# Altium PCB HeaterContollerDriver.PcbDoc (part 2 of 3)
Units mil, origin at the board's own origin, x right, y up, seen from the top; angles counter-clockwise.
Board outline 11550 x 4775 mil, 6 copper layers (Top Layer, GND1, P, N, GND2, Bottom Layer), stack 62.668 mil thick; 274 components, 133 nets, 711 pads, 145 vias.
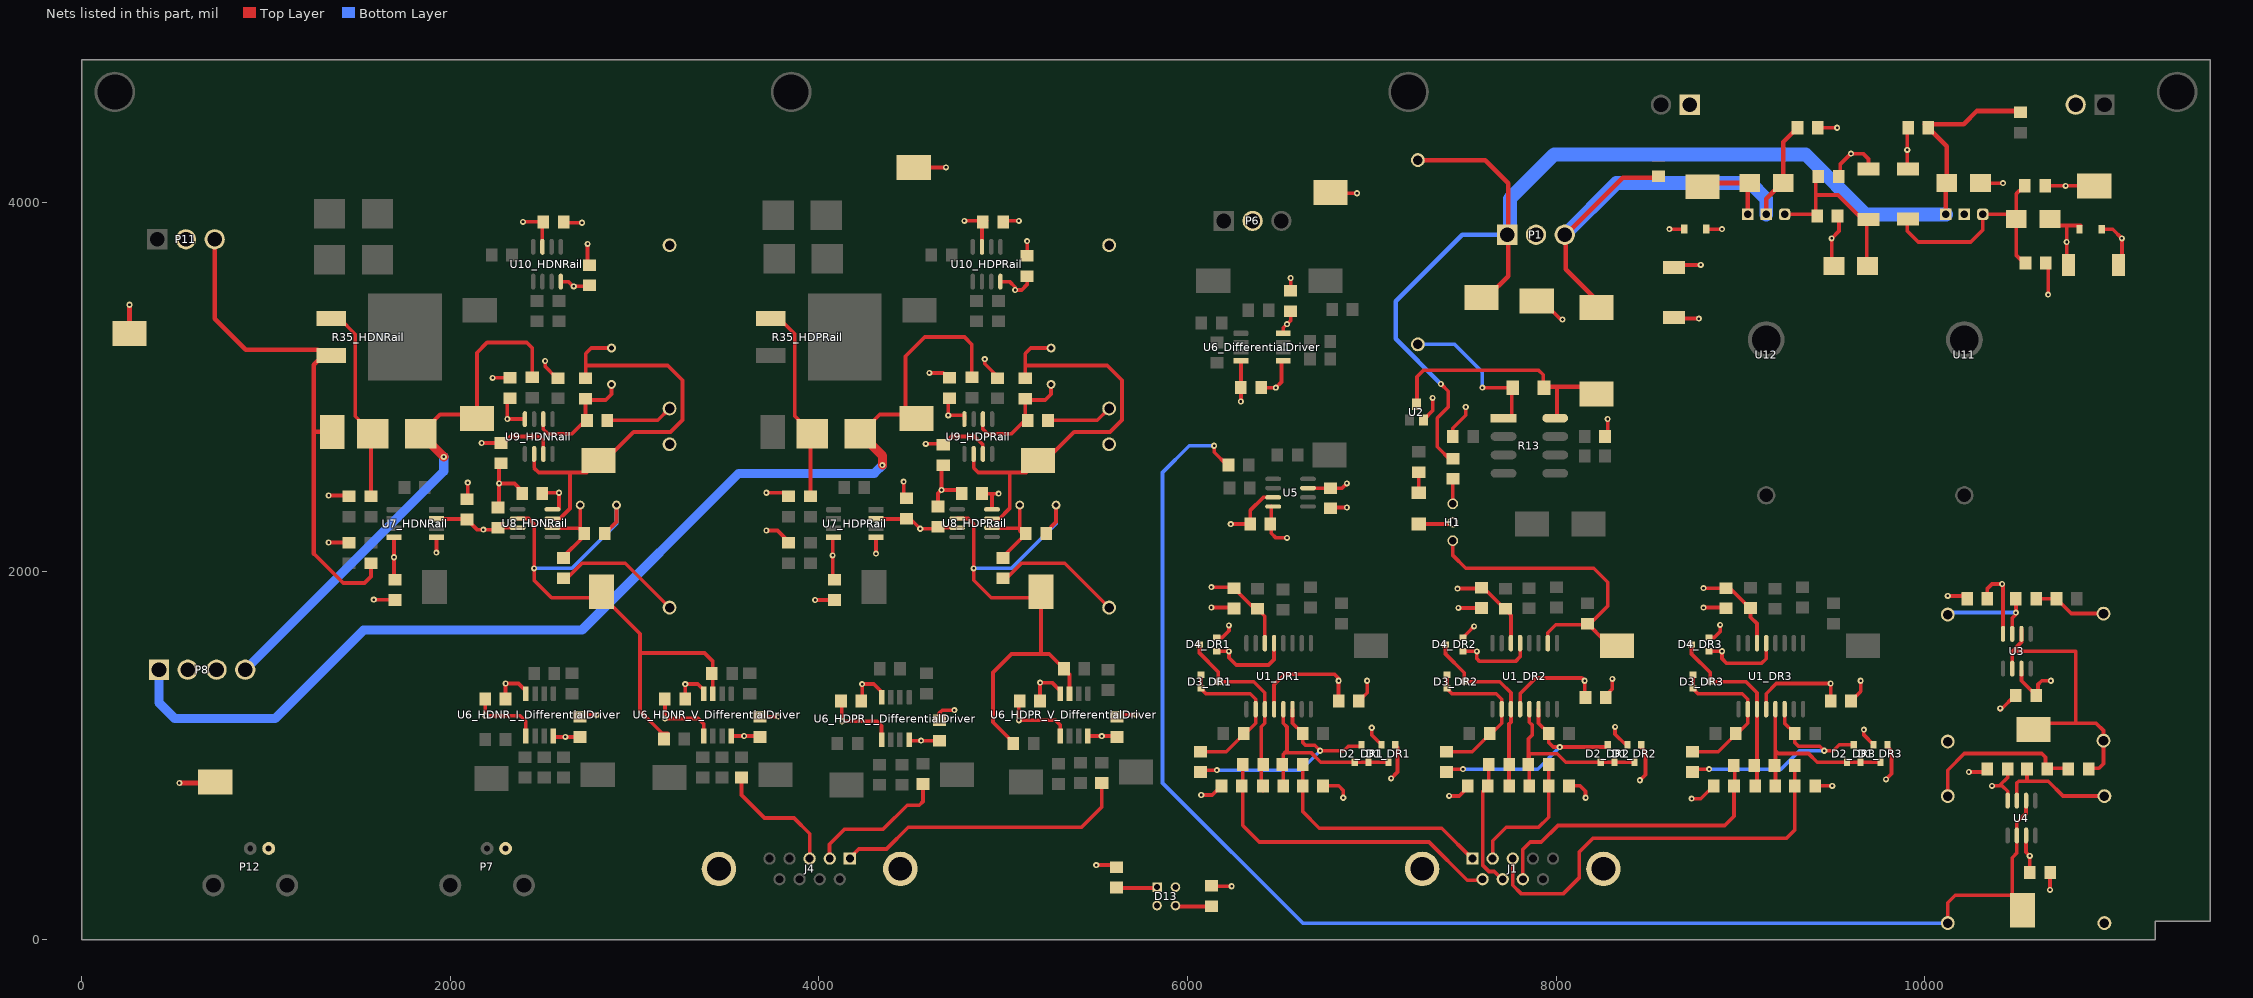
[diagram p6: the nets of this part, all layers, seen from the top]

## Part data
C1_DR1 C1_DR2 C1_DR3: library part MYCAP, "CAP 3.3nF 50V PPS 1206", Digikey Part Number=PCF1302CT-ND, Manufacturers Part Number=ECH-U1H332GX5, Tolerance=3%
C2_DR1 C2_DR2 C2_DR3 C3_DR1 C3_DR2 C3_DR3 C6 C7 C10 C11 C12 C13 C14_DifferentialDriver C14_HDNR_I_DifferentialDriver C14_HDNR_V_DifferentialDriver C14_HDPR_I_DifferentialDriver C14_HDPR_V_DifferentialDriver C15_DifferentialDriver C15_HDNR_I_DifferentialDriver C15_HDNR_V_DifferentialDriver C15_HDPR_I_DifferentialDriver C15_HDPR_V_DifferentialDriver C16_HDNRail C16_HDPRail C17_HDNRail C17_HDPRail C20_HDNRail C20_HDPRail C21_HDNRail C21_HDPRail C24_HDNRail C24_HDPRail C25_HDNRail C25_HDPRail C26_HDNRail C26_HDPRail C27_HDNRail C27_HDPRail C29 C33: library part MYCAP, "CAP 1.0UF 50V CERAMIC F 1206", Digikey Part Number=1276-1068-1-ND, Tolerance=5%
C4 C5 C8 C9: library part CAP_Radial_3.9uF_250v, Digikey Part Number=P10986-ND, Manufacturers Part Number=ECQ-E2395JB, Supplier Part Number 1=P14641-ND, Tolerance=3%
C18_HDNRail C18_HDPRail C19_HDNRail C19_HDPRail: library part CAP_Radial_6800pF_Polyester, Digikey Part Number=399-19323-1-ND, Manufacturers Part Number=R82EC1680DQ50J, Tolerance=5%
C22_HDNRail C22_HDPRail C23_HDNRail C23_HDPRail: library part CAP_10uF_Polyester, "Cap Film 10uF 100v +-5% 0.886inch", Digikey Part Number=P14629-ND, Manufacturers Part Number=ECQ-E1106JF, Tolerance=3%
C28 C30 C31 C32: library part CAP_2917_10µF_50v, Digikey Part Number=478-13267-1-ND, Manufacturers Part Number=TCJD106M050R0120, Tolerance=5%
D1_DR1 D1_DR2 D1_DR3 D2_DR1 D2_DR2 D2_DR3 D3_DR1 D3_DR2 D3_DR3 D4_DR1 D4_DR2 D4_DR3: "DUAL SERIES DIODE.", Digikey Part Number=BAS70-04LT1GOSCT-ND, Manufacturers Part Number=BAS70-04LT1G
D5 D6: library part DIODE_SE20AFJ-M3/6A, Digikey Part Number=SE20AFJ-M3/6AGICT-ND, Manufacturers Part Number=SE20AFJ-M3/6A
D7 D8 D10 D12: library part DIODE_S1BB, Digikey Part Number=S1BB-FDICT-ND, Manufacturers Part Number=S1BB-13-F
D9 D11: library part "DIODE RB160M-60TR", Digikey Part Number=RBR1MM60ATFCT-ND, Manufacturers Part Number=RBR1MM60ATFTR
D13: library part "Dual Stacked LED", "Dual Green LED", Supplier Part Number 1=67-1321-ND
F1_HDNRail F1_HDPRail F2_HDNRail F2_HDPRail F3_HDNRail F3_HDPRail: library part "SMD FUSE 1AMP", Digikey Part Number=F1303CT-ND, Manufacturers Part Number=0154001.DRT, Supplier Part Number 1=F1222CT-ND
H1: library part Header_3P, Digikey Part Number=S1011EC-03-ND, Manufacturers Part Number=PRPC003SAAN-RC
J1: library part DB9M, "Plug Assembly, 9 Position, Right Angle, .318 Series", Supplier Part Number 1=664-6E17C009PAJ121-ND
J4: library part "D Connector 9", "Receptacle Assembly, 9 Position, Right Angle", Digikey Part Number=A32117-ND, Manufacturers Part Number=5747844-4
P1 P6 P11: "Header, 3-Pin, Right Angle", Digikey Part Number=WM5236-ND
P7 P12: "BNC Straight Away Connector", Digikey Part Number=A144890-ND, Manufacturers Part Number=5227161-7
P8: "Header, 4-Pin, Right Angle", Digikey Part Number=WM5237-ND
P13 P14: library part "Header 2p 0.156inch", Digikey Part Number=A31676-ND, Manufacturers Part Number=3-641208-2, Supplier Part Number 1=A31688-ND
R1_DR1 R1_DR2 R1_DR3 R11_DR1 R11_DR2 R11_DR3: library part MYRES, "Resistor", 'Manufacturers Part Number=ERA-8AEB3011V, Digikey Part Number=P3.01KBCCT-ND, Tolerance=0.1%
R2_DR1 R2_DR2 R2_DR3 R10_DR1 R10_DR2 R10_DR3: library part MYRES, "Resistor", 'Manufacturers Part Number=ERA-8AEB104V, Digikey Part Number=P100KBCCT-ND, Tolerance=0.1%
R3_DR1 R3_DR2 R3_DR3 R9_DR1 R9_DR2 R9_DR3: library part MYRES, 'Manufacturers Part Number=ERA-8AEB3011V, Digikey Part Number=P2.26KBCCT-ND, Manufacturers Part Number=ERA-8AEB2261V, Tolerance=0.1%
R4_DR1 R4_DR2 R4_DR3 R7_DR1 R7_DR2 R7_DR3: library part MYRES, "Resistor", 'Manufacturers Part Number=ERA-8AEB102V, Digikey Part Number=P1.0KBCCT-ND, Tolerance=0.1%
R5_DR1 R5_DR2 R5_DR3 R8_DR1 R8_DR2 R8_DR3 R14 R15 R16 R28_DifferentialDriver R28_HDNR_I_DifferentialDriver R28_HDNR_V_DifferentialDriver R28_HDPR_I_DifferentialDriver R28_HDPR_V_DifferentialDriver R31_DifferentialDriver R31_HDNR_I_DifferentialDriver R31_HDNR_V_DifferentialDriver R31_HDPR_I_DifferentialDriver R31_HDPR_V_DifferentialDriver R44_HDNRail R44_HDPRail R45_HDNRail R45_HDPRail R46_HDNRail R46_HDPRail: library part Res3, "Resistor", Digikey Part Number=HCJ1206ZT0R00CT-ND, Tolerance=0.1%
R6_DR1 R6_DR2 R6_DR3: library part MYRES, "Resistor", Tolerance=0.1%
R12: library part Axial_TH_Res_1.30K_5W, Digikey Part Number=1.3KW-5-ND, Manufacturers Part Number=SQP500JB-1K3, Tolerance=0.1%
R13: library part RELAY_G6K-2F-TR-DC12, Digikey Part Number=Z113-ND, Manufacturers Part Number="G6K-2F DC12", Tolerance=0.1%
R17 R18: library part 1206_Res_3.9K, Digikey Part Number=P3.9KBCCT-ND, Manufacturers Part Number=ERA-8AEB392V, Tolerance=0.1%
R19 R20 R21 R22: library part MYRES, "39.2K Film Resistor", 'Manufacturers Part Number=ERA-8AEB3922V, Digikey Part Number=P39.2KBCCT-ND, Tolerance=0.1%
R23 R24 R25 R42_HDNRail R42_HDPRail R51 R52 R53 R54: library part 1206_Res_10K, "SMD 1206 Resistor 10K 0.25W 0.1%", Digikey Part Number=RNCP1206FTD10K0CT-ND, Manufacturers Part Number=RNCP1206FTD10K0, Tolerance=0.1%
R26_DifferentialDriver R26_HDNR_I_DifferentialDriver R26_HDNR_V_DifferentialDriver R26_HDPR_I_DifferentialDriver R26_HDPR_V_DifferentialDriver R27_DifferentialDriver R27_HDNR_I_DifferentialDriver R27_HDNR_V_DifferentialDriver R27_HDPR_I_DifferentialDriver R27_HDPR_V_DifferentialDriver R29_DifferentialDriver R29_HDNR_I_DifferentialDriver R29_HDNR_V_DifferentialDriver R29_HDPR_I_DifferentialDriver R29_HDPR_V_DifferentialDriver R30_DifferentialDriver R30_HDNR_I_DifferentialDriver R30_HDNR_V_DifferentialDriver R30_HDPR_I_DifferentialDriver R30_HDPR_V_DifferentialDriver R43_HDNRail R43_HDPRail: library part Res3, "Resistor", 'Manufacturers Part Number=TNPW12064K99BEEA, Digikey Part Number=TNP4.99KACCT-ND, Tolerance=0.1%
R32_HDNRail R32_HDPRail: library part 1206_Res_5.49K, Digikey Part Number=P2.61KBCCT-ND, Manufacturers Part Number=ERA-8AEB2611V, Tolerance=0.1%
R33_HDNRail R33_HDPRail R34_HDNRail R34_HDPRail R36_HDNRail R36_HDPRail R37_HDNRail R37_HDPRail: library part 1206_Res_100K, Digikey Part Number=P100KBCCT-ND, Manufacturers Part Number=ERA-8AEB104V, Tolerance=0.1%
R35_HDNRail R35_HDPRail: library part RES_D2PAK_1R00, 'Manufacturers Part Number=PWR263S-35-1R00F, Digikey Part Number=PWR163S-25-R100FECT-ND, Manufacturers Part Number=PWR163S-25-R100FE, Supplier Part Number 1=PWR263S-35-1R00F-ND, Tolerance=0.1%
R38_HDNRail R38_HDPRail R39_HDNRail R39_HDPRail: library part 1206_Res_23.2K, Digikey Part Number=P23.2KBCDKR-ND, Manufacturers Part Number=ERA-8AEB2322V, Supplier Part Number 1=P23.2KBCCT-ND, Tolerance=0.1%
R40_HDNRail R40_HDPRail R41_HDNRail R41_HDPRail: library part 1206_Res_1.58K, Digikey Part Number=P1.58KBCDKR-ND, Manufacturers Part Number=ERA-8AEB1581V, Tolerance=0.1%
R47: library part 1206_Res_249, Digikey Part Number=P249BCCT-ND, Manufacturers Part Number=ERA-8AEB2490V, Tolerance=0.1%
R48: library part 1206_Res_2.74K, Digikey Part Number=P2.74KBCCT-ND, Manufacturers Part Number=ERA-8AEB2741V, Tolerance=0.1%
R49: library part 1206_Res_1.33K, Digikey Part Number=P1.33KBCCT-ND, Manufacturers Part Number=ERA-8AEB1331V, Tolerance=0.1%
R50: library part 1206_Res_120R, Digikey Part Number=P120BCCT-ND, Manufacturers Part Number=ERA-8AEB121V, Tolerance=0.1%
TP1_DR1 TP1_DR2 TP1_DR3 TP2 TP3 TP4 TP5 TP6 TP7 TP8_DifferentialDriver TP8_HDNR_I_DifferentialDriver TP8_HDNR_V_DifferentialDriver TP8_HDPR_I_DifferentialDriver TP8_HDPR_V_DifferentialDriver TP9_DifferentialDriver TP9_HDNR_I_DifferentialDriver TP9_HDNR_V_DifferentialDriver TP9_HDPR_I_DifferentialDriver TP9_HDPR_V_DifferentialDriver TP10_HDNRail TP10_HDPRail TP11_HDNRail TP11_HDPRail TP12_HDNRail TP12_HDPRail TP13_HDNRail TP13_HDPRail TP14_HDNRail TP14_HDPRail TP15 TP16 TP17 TP18 TP19 TP20_HDNRail TP20_HDPRail TP21 TP22 TP23 TP24: "PCB Testpoint", 'Manufacturers Part Number=5016, Digikey Part Number=36-5016CT-ND
U1_DR1 U1_DR2 U1_DR3: "Quad Low Noise, High-Speed Precision Operational Amplifier", 'Manufacturers Part Number=LT1125CSW#PBF, Digikey Part Number=505-LT1125CSW#PBF-ND
U2: library part MMBT2222A_NPN, 'Manufacturers Part Number=MMBT2222A, Digikey Part Number=MMBT2222ALT1GOSCT-ND
U3 U4 U5 U8_HDNRail U8_HDPRail U9_HDNRail U9_HDPRail U10_HDNRail U10_HDPRail: library part ADOP27AQ, "Ultra-Low Noise, Precision Operational Amplifier", Digikey Part Number=OP27GSZ-REEL7CT-ND
U6_DifferentialDriver U6_HDNR_I_DifferentialDriver U6_HDNR_V_DifferentialDriver U6_HDPR_I_DifferentialDriver U6_HDPR_V_DifferentialDriver: "High-Speed, Low-Power Dual Operational Amplifier", 'Manufacturers Part Number=AD8672ARZ-REEL7, Digikey Part Number=505-AD8672ARZ-REEL7CT-ND
U7_HDNRail U7_HDPRail: library part AD620, "Low power instrumentation amplifier", 'Manufacturers Part Number=AD620BRZ-R7, Digikey Part Number=AD620BRZ-R7CT-ND
U11: library part LM317, Digikey Part Number=LM317TNS/NOPB-ND, Manufacturers Part Number=LM317T/NOPB
U12: library part "LDO LM337", Digikey Part Number=LM337TNS/NOPB-ND, Manufacturers Part Number=LM337TNS/NOPB

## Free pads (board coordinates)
  round 220 hole 190: 1(180,4600) 2(3850,4600) 3(7200,4600) 4(11370,4600)
  round 33 hole 14: 6(6540,3340) 7(6560,3590) 8(6290,2920) 9(6479.49,2995)

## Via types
v1: diameter 33, hole 14, Top Layer to Bottom Layer, 145 vias

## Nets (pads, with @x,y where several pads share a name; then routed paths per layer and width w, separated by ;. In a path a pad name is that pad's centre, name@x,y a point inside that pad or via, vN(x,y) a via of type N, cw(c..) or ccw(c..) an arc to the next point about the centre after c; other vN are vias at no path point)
+15: C2_DR1.1 C2_DR2.1 C2_DR3.1 C6.1 C7.1 C12.1 C14_DifferentialDriver.2 C14_HDNR_I_DifferentialDriver.2 C14_HDNR_V_DifferentialDriver.2 C14_HDPR_I_DifferentialDriver.2 C14_HDPR_V_DifferentialDriver.2 C16_HDNRail.2 C16_HDPRail.2 C20_HDNRail.1 C20_HDPRail.1 C21_HDNRail.1 C21_HDPRail.1 C26_HDNRail.1 C26_HDPRail.1 C28.1 D1_DR1.2 D1_DR2.2 D1_DR3.2 D4_DR1.2 D4_DR2.2 D4_DR3.2 D7.2 D8.1 D9.1 pad.6 R47.2 R51.2 TP16.1 U1_DR1.4 U1_DR2.4 U1_DR3.4 U3.7 U4.7 U5.7 U6_DifferentialDriver.8 U6_HDNR_I_DifferentialDriver.8 U6_HDNR_V_DifferentialDriver.8 U6_HDPR_I_DifferentialDriver.8 U6_HDPR_V_DifferentialDriver.8 U7_HDNRail.7 U7_HDPRail.7 U8_HDNRail.7 U8_HDPRail.7 U9_HDNRail.7 U9_HDPRail.7 U10_HDNRail.7 U10_HDPRail.7 U11.2 | length 7070.1
  Top Layer w20: U7_HDNRail.7@1925,2283 2086.88,2283 C16_HDNRail.2@2090,2279.88 2144.88,2225 v1(2180,2225) 2250.12,2225 C21_HDNRail.1@2260,2234.88 U8_HDNRail.7@2365.51,2234.88 ; v1(2170,2695) 2290,2695 2325,2730 2485,2730 2505,2710 U9_HDNRail.7@2505,2635.39 U9_HDNRail.7@2505,2625 ; v1(2395,3895) C26_HDNRail.1@2504.88,3895 2500,3890.12 U10_HDNRail.7@2500,3759.49 ; U6_HDNR_I_DifferentialDriver.8@2565.12,1100 v1(2625,1100) C14_HDNR_I_DifferentialDriver.2@2705,1100 ; U6_HDNR_V_DifferentialDriver.8@3525.12,1105 v1(3595,1105) 3674.88,1105 C14_HDNR_V_DifferentialDriver.2@3680,1099.88 ; U7_HDPRail.7@4310,2283 C16_HDPRail.2@4473.24,2283 ; C16_HDPRail.2@4485,2294.76 v1(4550,2229.76) C21_HDPRail.1@4640,2229.76 ; U6_HDPR_I_DifferentialDriver.8@4495,1080 v1(4555,1080) C14_HDPR_I_DifferentialDriver.2@4654.88,1080 ; v1(4580,2690) C20_HDPRail.1@4679.88,2690 ; C21_HDPRail.1@4650,2239.76 4654.76,2235 U8_HDPRail.7@4750.51,2235 ; C20_HDPRail.1@4675,2685.12 C20_HDPRail.1@4679.88,2690 ; v1(4790,3900) C26_HDPRail.1@4910,3900 ; U10_HDPRail.7@4885,3759.49 C26_HDPRail.1@4885,3890 ; U9_HDPRail.7@4890,2635.39 4890,2685 4845,2730 4719.88,2730 C20_HDPRail.1@4679.88,2690 ; U6_HDPR_V_DifferentialDriver.8@5460.12,1104.76 v1(5535,1104.76) C14_HDPR_V_DifferentialDriver.2@5611.88,1104.76 ; v1(5505,405) 5611,405 R51.2@5615,401 ; D4_DR1.2@6159.49,1639.69 6188.74,1639.69 6225,1675.94 v1(6225,1704.92) ; U1_DR1.4@6469.88,1265 6469.88,1382.64 6527.24,1440 6797.76,1440 6819.88,1417.87 C2_DR1.1@6819.88,1294.76 ; U6_DifferentialDriver.8@6520,3290 6520,3320 pad.6@6540,3340 6560,3360 C14_DifferentialDriver.2@6560,3409.88 ; U5.7@6653.98,2450 C12.1@6794.37,2450 ; C12.1@6794.49,2450.12 6839.49,2450.12 v1(6865,2475.62) ; C2_DR1.1@6819.88,1280 C2_DR1.1@6819.88,1294.76 ; C2_DR1.1@6820.24,1303.03 6828.5,1294.76 C2_DR1.1@6819.88,1294.76 ; v1(7000,1150) 7000,1110.35 D1_DR1.2@7052.97,1057.38 ; D4_DR2.2@7494.49,1639.8 7517.34,1662.66 7517.66,1662.66 v1(7555,1700) ; U1_DR2.4@7804.88,1250.87 7804.88,1334.88 7890,1420 8140,1420 v1(8154.88,1405.12) C2_DR2.1@8154.88,1305 ; v1(8320,1155) 8320,1115 8377.87,1057.13 D1_DR2.2@8387.6,1057.13 ; D4_DR3.2@8829.49,1639.8 8858.74,1639.8 8890,1671.06 v1(8890,1708.39) ; U1_DR3.4@9139.88,1250.87 9139.88,1334.88 9195,1390 v1(9489.88,1390) 9489.98,1294.88 9490,1280 C2_DR3.1@9489.88,1294.88 ; v1(9670,1140) 9670,1110 D1_DR3.2@9722.74,1057.26 ; D7.2@10302.5,4105.5 10303,4105 v1(10425,4105) ; U3.7@10525,1460 10525,1404.88 10599.88,1330 10605.12,1330 10615,1339.88 10615,1384.89 10635.11,1405 v1(10685,1405) ; U4.7@10550,560 10550,474.88 v1(10569.88,455) C6.1@10569.88,365 ; R47.2@10661.5,4090 v1(10765,4090) TP16.1@10855,4090 ; D8.1@10665,3915 10705,3875 10770,3875 ; C28.1@10780,3660 10770,3670 v1(10770,3785.5) 10770,3875 ; D9.1@10840,3855 10840,3870 10845,3875 10770,3875
  other v1: 6820.24,1405
+18: C29.2 D7.1 P1.1 R12.2 R18.1 R53.2 TP15.1 U11.3 | length 6896.6
  Top Layer w20: v1(7375,3015) 7415,2975 7415,2890 7355,2830 7355,2675 R18.1@7430,2600 ; D7.1@10115,4100.5 D7.1@10120,4105.5
  Top Layer w25: R12.2@7250,4230 7615,4230 7740,4105 7740,3600 7630,3490 TP15.1@7630,3480 ; U11.3@10115,3935.5 D7.1@10115,4100.5 ; D7.1@10120,4105.5 10120,4305.5 10000.5,4425 10212.5,4425 10284,4496.5 R53.2@10520.12,4496.5
  Bottom Layer w25: v1(7375,3015) 7130,3260 7130,3465 7490,3825 P1.1@7735,3825
  Bottom Layer w75: P1.1@7735,3825 7749.76,3839.76 7749.76,4020.5 7989.76,4260.5 9354.76,4260.5 9679.76,3935.5 U11.3@10115,3935.5
-15: C3_DR1.1 C3_DR2.1 C3_DR3.1 C10.1 C11.1 C13.1 C15_DifferentialDriver.2 C15_HDNR_I_DifferentialDriver.2 C15_HDNR_V_DifferentialDriver.2 C15_HDPR_I_DifferentialDriver.2 C15_HDPR_V_DifferentialDriver.2 C17_HDNRail.1 C17_HDPRail.1 C24_HDNRail.1 C24_HDPRail.1 C25_HDNRail.1 C25_HDPRail.1 C27_HDNRail.1 C27_HDPRail.1 C32.2 D1_DR1.1 D1_DR2.1 D1_DR3.1 D4_DR1.1 D4_DR2.1 D4_DR3.1 D10.2 D11.2 D12.1 pad.8 R50.1 R52.1 TP19.1 U1_DR1.13 U1_DR2.13 U1_DR3.13 U3.4 U4.4 U5.4 U6_DifferentialDriver.4 U6_HDNR_I_DifferentialDriver.4 U6_HDNR_V_DifferentialDriver.4 U6_HDPR_I_DifferentialDriver.4 U6_HDPR_V_DifferentialDriver.4 U7_HDNRail.4 U7_HDPRail.4 U8_HDNRail.4 U8_HDPRail.4 U9_HDNRail.4 U9_HDPRail.4 U10_HDNRail.4 U10_HDPRail.4 U12.3 | length 7100.9
  Top Layer w20: U7_HDNRail.4@1695,2183 v1(1695,2075) 1695,1958.12 C17_HDNRail.1@1700,1953.12 ; C15_HDNR_I_DifferentialDriver.2@2300.12,1305 2300.12,1350.01 v1(2300.12,1390) 2370,1390 2410.12,1349.88 U6_HDNR_I_DifferentialDriver.4@2410.12,1335 ; C24_HDNRail.1@2310,2945 v1(2310,2825) 2404.37,2825 U9_HDNRail.4@2405,2824.37 ; C25_HDNRail.1@2500.12,2419.88 2495,2425 v1(2590,2425) 2590,2340 2584.88,2334.88 U8_HDNRail.4@2554.49,2334.88 ; U10_HDNRail.4@2600,3570.51 2640,3570.51 2665.51,3545 v1(2670,3545) 2735.24,3545 C27_HDNRail.1@2740,3549.76 ; C15_HDNR_V_DifferentialDriver.2@3275.12,1329.88 3275.12,1374.89 v1(3275.12,1386.82) 3343.18,1386.82 3375,1355 U6_HDNR_V_DifferentialDriver.4@3375,1334.88 ; C17_HDPRail.1@4075,1945 v1(4075,2085) 4075,2178 U7_HDPRail.4@4080,2183 U7_HDPRail.4@4093,2183 ; C15_HDPR_I_DifferentialDriver.2@4235.12,1275.12 v1(4235.12,1386.93) 4298.07,1386.93 4340,1345 U6_HDPR_I_DifferentialDriver.4@4340,1315 ; C24_HDPRail.1@4710,2937.88 4701.88,2946 v1(4701.88,2845) 4789.88,2845 4790,2844.88 U9_HDPRail.4@4790,2824.37 ; C25_HDPRail.1@4900.12,2419.88 v1(4975,2419.88) ; U8_HDPRail.4@4939.49,2335 4939.49,2419.37 ; U10_HDPRail.4@4985,3570.51 5034.49,3570.51 5065,3540 v1(5065,3525) 5100.24,3525 5130,3554.76 C27_HDPRail.1@5130,3599.88 ; C15_HDPR_V_DifferentialDriver.2@5200.12,1294.65 v1(5200.12,1394.88) 5265.12,1394.88 5310,1350 U6_HDPR_V_DifferentialDriver.4@5310,1334.88 ; R52.1@6130,300 6140,290 v1(6240,290) ; v1(6130,1802.28) C3_DR1.1@6265,1802.28 ; D4_DR1.1@6159.49,1564.88 6159.61,1564.76 v1(6225,1564.76) 6225,1530 6265,1490 6439.88,1490 6469.88,1520 U1_DR1.13@6469.88,1609.02 ; pad.8@6290,2920 U6_DifferentialDriver.4@6290,3140 ; U5.4@6455,2350 6455,2205 6480,2180 v1(6540,2180) ; v1(7105,875) 7140,910 7140,1044.41 D1_DR1.1@7127.4,1057.01 ; v1(7470,1799.88) C3_DR2.1@7587.24,1799.88 ; D4_DR2.1@7494.49,1565 7494.72,1564.76 v1(7570,1564.76) 7570,1525 7585,1510 7780,1510 7804.88,1534.88 U1_DR2.13@7804.88,1609.13 ; v1(8455,865) 8485,895 8485,1020 8462.4,1042.6 D1_DR2.1@8462.4,1057.13 ; C32.2@8639.5,3647 8653.5,3661 v1(8785,3661) ; v1(8800,1802) 8922.24,1802 C3_DR3.1@8922.24,1797.28 ; D11.2@8815.5,3855.5 8816,3855 v1(8900,3855) ; D4_DR3.1@8829.49,1565 8858.75,1565 8858.86,1564.88 v1(8900,1564.88) 8900,1525 8925,1500 9115,1500 9139.88,1524.88 U1_DR3.13@9139.88,1609.13 ; D12.1@9040,4095.5 D12.1@9050,4105.5 ; D10.2@9507.5,3655.5 9495,3668 v1(9495,3805) 9535,3845 R50.1@9535,3925.5 ; v1(9790,870) 9820,900 9820,1025 9797.4,1047.6 D1_DR3.1@9797.4,1057.13 ; C10.1@10340.12,1850 10340.12,1905.12 10365,1930 v1(10420,1930) 10425,1925 U3.4@10425,1685 ; v1(10365,834.76) 10404.89,834.76 ; U4.4@10450,790 10450,804.76 10420,834.76 10404.89,834.76 ; C11.1@10450.12,925 10450.12,879.99 10404.89,834.76
  Top Layer w25: TP19.1@8815,4105.5 D12.1@9050,4105.5 ; U12.3@9040,3935.5 D12.1@9040,4095.5
-18: C33.1 D12.2 P1.3 R54.2 TP18.1 U12.2 | length 2930.7
  Top Layer w25: TP18.1@8230,3480 8210,3480 8052,3638 8052,3825 8361.5,4134.5 R54.2@8555,4134.5 ; U12.2@9140,3935.5 9140,4020 9232.5,4112.5 9232.5,4328.12 C33.1@9309.88,4405.5
  Bottom Layer w75: P1.3@8047,3825 8327,4105 9055,4105 9140,4020 U12.2@9140,3935.5
GND: C2_DR1.2 C2_DR2.2 C2_DR3.2 C3_DR1.2 C3_DR2.2 C3_DR3.2 C6.2 C7.2 C8.1 C9.1 C10.2 C11.2 C12.2 C13.2 C14_DifferentialDriver.1 C14_HDNR_I_DifferentialDriver.1 C14_HDNR_V_DifferentialDriver.1 C14_HDPR_I_DifferentialDriver.1 C14_HDPR_V_DifferentialDriver.1 C15_DifferentialDriver.1 C15_HDNR_I_DifferentialDriver.1 C15_HDNR_V_DifferentialDriver.1 C15_HDPR_I_DifferentialDriver.1 C15_HDPR_V_DifferentialDriver.1 C16_HDNRail.1 C16_HDPRail.1 C17_HDNRail.2 C17_HDPRail.2 C20_HDNRail.2 C20_HDPRail.2 C21_HDNRail.2 C21_HDPRail.2 C22_HDNRail.1 C22_HDPRail.1 C23_HDNRail.1 C23_HDPRail.1 C24_HDNRail.2 C24_HDPRail.2 C25_HDNRail.2 C25_HDPRail.2 C26_HDNRail.2 C26_HDPRail.2 C27_HDNRail.2 C27_HDPRail.2 C28.2 C29.1 C30.2 C31.1 C32.1 C33.2 D9.2 D11.1 D13.2 D13.3 J1.10 J1.11 J4.10 J4.11 P1.2 P6.2 P7.2 P8.2 P8.3 P11.2 P12.2 P13.2 P14.1 pad.7 pad.9 R2_DR1.1 R2_DR2.1 R2_DR3.1 R3_DR1.2 R3_DR2.2 R3_DR3.2 R10_DR1.2 R10_DR2.2 R10_DR3.2 R14.1 R15.2 R33_HDNRail.2 R33_HDPRail.2 R37_HDNRail.1 R37_HDPRail.1 R43_HDNRail.1 R43_HDPRail.1 R48.1 R49.2 TP17.1 TP21.1 TP22.1 TP23.1 TP24.1 U1_DR1.14 U1_DR2.14 U1_DR3.14 U2.2 U5.3 U6_DifferentialDriver.5 U6_HDNR_I_DifferentialDriver.5 U6_HDNR_V_DifferentialDriver.5 U6_HDPR_I_DifferentialDriver.5 U6_HDPR_V_DifferentialDriver.5 U7_HDNRail.5 U7_HDPRail.5 | length 11394.6
  Top Layer w20: TP23.1@720,850 TP23.1@725,855 ; v1(1340,2155) 1444,2155 R33_HDNRail.2@1450,2161 ; v1(1340,2410) 1447,2410 R37_HDNRail.1@1450,2413 ; v1(1585,1845) C17_HDNRail.2@1700,1845 ; v1(1925,2100) U7_HDNRail.5@1925,2183 ; C16_HDNRail.1@2095,2388.12 v1(2095,2480) ; C15_HDNR_I_DifferentialDriver.1@2189.88,1305 v1(2189.88,1215) 2380,1215 2410.12,1184.88 U6_HDNR_I_DifferentialDriver.5@2410.12,1105 ; v1(2230,3048.12) 2279.99,3048.12 C24_HDNRail.2@2325,3048.12 ; C21_HDNRail.2@2260,2345.12 2265,2345.12 v1(2265,2475.62) ; C20_HDNRail.2@2279.88,2584.76 2265,2569.88 v1(2265,2475.62) ; C25_HDNRail.2@2404.88,2419.88 2349.14,2475.62 v1(2265,2475.62) ; v1(2515,3140) 2515,3110 2570.12,3054.88 R43_HDNRail.1@2585,3054.88 ; C26_HDNRail.2@2615.12,3895 2615.12,3890 v1(2715,3890) ; C14_HDNR_I_DifferentialDriver.1@2680.12,1220.12 C14_HDNR_I_DifferentialDriver.1@2715,1220.12 ; C14_HDNR_I_DifferentialDriver.1@2705,1210.12 C14_HDNR_I_DifferentialDriver.1@2715,1220.12 ; C14_HDNR_I_DifferentialDriver.1@2730.12,1230 2724.88,1230 C14_HDNR_I_DifferentialDriver.1@2715,1220.12 ; C27_HDNRail.2@2745,3650 v1(2745,3775) ; v1(2795,1220.12) C14_HDNR_I_DifferentialDriver.1@2715,1220.12 ; C15_HDNR_V_DifferentialDriver.1@3164.88,1320 3165,1319.88 v1(3165,1200) 3345,1200 3375,1170 U6_HDNR_V_DifferentialDriver.5@3375,1104.88 ; C14_HDNR_V_DifferentialDriver.1@3675,1210.12 C14_HDNR_V_DifferentialDriver.1@3680,1210.12 v1@3765,1210.12 ; v1(3715,2220) 3776,2220 R33_HDPRail.2@3835,2161 ; v1(3715,2425) 3823,2425 R37_HDPRail.1@3835,2413 ; v1(3980,1842.88) C17_HDPRail.2@4085,1842.88 ; C15_HDPR_I_DifferentialDriver.1@4125,1294.88 v1(4125,1185.12) 4315,1185.12 4340,1160.12 U6_HDPR_I_DifferentialDriver.5@4340,1085 ; v1(4310,2095) U7_HDPRail.5@4310,2183 ; v1(4460,2485) 4460,2410 C16_HDPRail.1@4475,2395 ; TP21.1@4515,4190 v1(4690,4190) ; v1(4600,3075) 4675,3075 4701.88,3048.12 C24_HDPRail.2@4710,3048.12 ; C14_HDPR_I_DifferentialDriver.1@4655,1190.12 4655,1230.12 4670,1245.12 v1(4735,1245.12) ; C20_HDPRail.2@4665.63,2575.51 v1(4665.63,2440) ; C25_HDPRail.2@4789.88,2419.88 4769.76,2440 v1(4665.63,2440) ; v1(4900,3150) 4900,3124.88 R43_HDPRail.1@4970,3054.88 ; C26_HDPRail.2@5000.12,3895 5000.12,3900 v1(5085,3900) ; C15_HDPR_V_DifferentialDriver.1@5085,1289.76 v1(5085,1189.88) 5285.12,1189.88 5310,1165 U6_HDPR_V_DifferentialDriver.5@5310,1104.88 ; C27_HDPRail.2@5130,3710 C27_HDPRail.2@5130,3710.12 v1(5130,3790) ; C14_HDPR_V_DifferentialDriver.1@5605,1210 C14_HDPR_V_DifferentialDriver.1@5615,1210 ; C14_HDPR_V_DifferentialDriver.1@5615,1220 v1(5720,1220) ; v1(6074.76,785) 6135.12,785 R10_DR1.2@6184.88,834.76 ; v1(6130,1912.52) C3_DR1.2@6265.87,1912.52 ; v1(6235,2255) C13.2@6339.88,2255 6339.88,2328 6411.88,2400 U5.3@6465,2400 ; C3_DR1.2@6252.24,1907.4 R3_DR1.2@6359.76,1799.88 ; R3_DR1.2@6380,1794.88 6419.88,1755 U1_DR1.14@6419.88,1609.02 ; C15_DifferentialDriver.1@6399.72,2995 pad.9@6479.49,2995 6510,3025.51 U6_DifferentialDriver.5@6510,3130 ; C14_DifferentialDriver.1@6560,3520.12 pad.7@6560,3590 ; R2_DR1.1@6735.12,834.76 6820.24,834.76 6845,810 v1(6845,770) ; TP24.1@6775,4055 6780,4050 v1(6920,4050) ; C12.2@6794.49,2339.88 6799.61,2345 v1(6865,2345) ; C2_DR1.2@6930.12,1294.76 6975,1339.65 v1(6975,1405) ; U2.2@7280,2820 7330,2870 v1(7330,2940) ; v1(7420,780) 7475,780 7519.88,824.88 R10_DR2.2@7519.88,834.88 ; R15.2@7439.88,2730 7439.88,2775.01 7510,2845.12 v1(7510,2890) ; v1(7465,1905) 7610.12,1905 7755,1760.12 U1_DR2.14@7755,1595 ; TP17.1@7895,3480 7910,3480 8025,3365 v1(8035,3365) ; R2_DR2.1@8070.12,834.88 8130.12,834.88 8160,805 v1(8160,770) ; R14.1@8265.12,2730 8280,2715.12 v1(8280,2825) ; C2_DR2.2@8275,1295 8275,1330 8305,1360 v1(8305,1415) ; v1(8615,3855) 8694.5,3855 D11.1@8695,3855.5 ; C32.1@8639.5,3375 8644.5,3370 v1(8774.88,3370) ; v1(8735,765) 8785,765 R10_DR3.2@8854.88,834.88 ; v1(8800,1907.52) 8877.24,1907.52 C3_DR3.2@8922.24,1907.52 8942.48,1907.52 R3_DR3.2@9055,1795 ; R3_DR3.2@9055,1799.88 R3_DR3.2@9055,1795 ; U1_DR3.14@9089.88,1609.13 9089.88,1715.12 9055,1750 R3_DR3.2@9055,1795 ; R2_DR3.1@9405.12,834.88 9449.89,834.88 9450,834.76 v1(9498.5,834.76) ; C33.2@9420.12,4405.5 v1(9525,4405.5) ; R49.2@9541,4140.5 9541,4205.88 v1(9600.12,4265) 9665.5,4265 9695.12,4235.38 C31.1@9695.12,4180.5 ; C2_DR3.2@9600.12,1294.88 9652.4,1347.17 v1(9652.4,1404.88) ; C30.2@9905.12,4182.5 v1(9905.12,4285) 9905.12,4400.74 C29.1@9909.88,4405.5 ; v1(10125,1865) 10199.88,1865 10207.38,1872.5 C10.2@10229.88,1850 ; v1(10239.65,909.65) 10339.88,909.65 C11.2@10339.88,919.88 ; C11.2@10339.88,925 C11.2@10339.88,919.88 ; C11.2@10355,935 C11.2@10339.88,919.88 ; v1(10409.88,1255) 10409.88,1245 C7.2@10494.88,1330 ; R48.1@10665,3670.5 10670,3665.5 v1(10670,3500) ; v1(10680,270) 10680,319.88 10680.12,319.99 C6.2@10680.12,365 ; D9.2@10960.5,3855 11020,3855 v1(11070,3805) 11070,3678 C28.2@11052,3660 ; C21_HDPRail.2@4646.88,2360.88 4646.88,2421.25 v1(4665.63,2440) ; C21_HDPRail.2@4646.88,2360.88 4643,2357 4646.88,2353.12 C21_HDPRail.2@4646.88,2360.88 ; R10_DR3.2@8854.88,834.88 8854.88,825 8875,825 8865.12,834.88 R10_DR3.2@8854.88,834.88
  Top Layer w25: TP22.1@260,3290 v1(260,3445) ; v1(530,850) TP23.1@720,850
  other v1: 3780,1210
L: P11.3 R34_HDNRail.1 R35_HDNRail.3 TP20_HDNRail.1 | length 2813.4
  Top Layer w20: 1260,2095 1420,1935 1535,1935 1570,1970 R34_HDNRail.1@1570,2040 ; R35_HDNRail.3@1310,3169.88 R35_HDNRail.3@1355,3169.88
  Top Layer w25: P11.3@722,3800 722,3368 890,3200 1279.88,3200 1310,3169.88 1260,3119.88 1260,2755 ; 1260,2095 1260,2755 ; TP20_HDNRail.1@1370,2755 1260,2755
NetC1_DR1_1: C1_DR1.1 D3_DR1.3 D4_DR1.3 R7_DR1.1 U1_DR1.3 | length 1065.3
  Top Layer w20: D4_DR1.3@6065,1602.28 6065,1555 6167.24,1452.76 D3_DR1.3@6167.24,1399.88 6360,1399.88 6419.88,1340 U1_DR1.3@6419.88,1250.75 6419.88,1174.88 6400,1155 6400,844.65 C1_DR1.1@6409.88,834.76 C1_DR1.1@6409.88,809.17
NetC1_DR1_2: C1_DR1.2 D1_DR1.3 D2_DR1.1 D2_DR1.2 R4_DR1.1 U1_DR1.5 | length 1061.9
  Top Layer w20: R4_DR1.1@6514.88,964.76 6519.88,969.76 6519.88,1005.24 6529.65,1015 ; R4_DR1.1@6519.88,949.76 R4_DR1.1@6519.88,964.76 ; U1_DR1.5@6519.88,1250.75 6519.88,1174.76 6540,1154.65 6540,1025.35 6529.65,1015 ; C1_DR1.2@6520,834.76 6520,994.88 ; D1_DR1.3@7090,962.52 D2_DR1.2@6982.4,962.52 D2_DR1.1@6907.6,962.52 6722.48,962.52 6670,1015 6529.65,1015
NetC1_DR2_1: C1_DR2.1 D3_DR2.3 D4_DR2.3 R7_DR2.1 U1_DR2.3 | length 1045.7
  Top Layer w20: D4_DR2.3@7400,1602.4 7400,1550 7502.24,1447.76 D3_DR2.3@7502.24,1400 7695,1400 7754.88,1340.12 U1_DR2.3@7754.88,1250.87 ; C1_DR2.1@7745,819.88 7745,1169.88 7755,1179.88 U1_DR2.3@7755,1250
NetC1_DR2_2: C1_DR2.2 D1_DR2.3 D2_DR2.1 D2_DR2.2 R4_DR2.1 U1_DR2.5 | length 1064.8
  Top Layer w20: R4_DR2.1@7849.88,964.88 7849.88,1090 7870,1110.12 7870,1164.88 7854.88,1180 U1_DR2.5@7854.88,1250.87 ; R4_DR2.1@7854.88,949.88 R4_DR2.1@7854.88,964.88 ; 7854.88,1008.5 8006.5,1008.5 8052.36,962.64 D2_DR2.1@8242.6,962.64 D2_DR2.2@8317.4,962.64 D1_DR2.3@8425,962.64 ; C1_DR2.2@7855,834.88 7855,995
NetC1_DR3_1: C1_DR3.1 D3_DR3.3 D4_DR3.3 R7_DR3.1 U1_DR3.3 | length 1037.3
  Top Layer w20: D4_DR3.3@8735,1602.4 8735,1550 8837.24,1447.76 D3_DR3.3@8837.24,1400 9030,1400 9089.88,1340.12 U1_DR3.3@9089.88,1250.87 ; C1_DR3.1@9090,824.88 U1_DR3.3@9090,1250.75
NetC1_DR3_2: C1_DR3.2 D1_DR3.3 D2_DR3.1 D2_DR3.2 R4_DR3.1 U1_DR3.5 | length 1059.1
  Top Layer w20: R4_DR3.1@9184.88,964.88 9189.88,969.88 9189.88,1024.88 ; R4_DR3.1@9189.88,949.88 R4_DR3.1@9189.88,964.88 ; U1_DR3.5@9189.88,1250.87 9189.88,1024.88 ; C1_DR3.2@9190,834.88 9190,995 ; D1_DR3.3@9760,962.64 D2_DR3.2@9652.4,962.64 D2_DR3.1@9577.6,962.64 9417.36,962.64 9370,1010 9204.76,1010 9189.88,1024.88
NetC4_1: C4.1 R21.2 TP5.1 U3.2 U3.6 | length 1722.5
  Top Layer w20: U3.6@10475,1485 10475,1560 10475,1565 ; TP5.1@10520,1145 10520,1175 10820,1175 ; U3.2@10525,1685 10525,1615 10475,1565 ; R21.2@10890.12,930.12 10945.12,930.12 10970,955 C4.1@10970,1080 10970,1135 10930,1175 10820,1175 ; 10475,1565 10820,1565 10820,1175
NetC4_2: C4.2 R19.1 R20.2 | length 397
  Top Layer w20: R20.2@10605.12,1850 R19.1@10714.88,1850 10794.88,1770 C4.2@10969,1770
NetC5_1: C5.1 R25.1 TP6.1 U4.2 U4.6 | length 7788.9
  Top Layer w20: v1(6145,2680) 6145,2645 6215,2575 R25.1@6229.49,2575 ; C5.1@10125,90 10125,200 10166,241 10469,241 10475,235 10475,445 10500,470 10500,560 10500,635 10550,685 U4.2@10550,765
  Bottom Layer w20: v1(6145,2680) 6010,2680 5865,2535 5865,850 6625,90 C5.1@10125,90
NetC5_2: C5.2 R21.1 R22.2 | length 898.4
  Top Layer w20: C5.2@10125,779 10125,920 10215,1010 10635,1010 10655,990 10655,935.12 10660.12,930 R21.1@10779.88,930
NetC8_2: C8.2 R20.1 U3.3 | length 557.7
  Top Layer w20: U3.3@10475,1685 10475,1745.24 10494.88,1765.12 R20.1@10494.88,1850
  Bottom Layer w20: C8.2@10125,1764 10136,1775 10487.76,1775 10494.88,1767.88 v1(10494.88,1775)
NetC9_2: C9.2 R22.1 U4.3 | length 669.4
  Top Layer w20: U4.3@10500,765 10500,790 10500,850 10510,860 10554.88,860 ; R22.1@10554.88,925 10554.88,860 ; C9.2@10980,785 10975,780 10750,780 10670,860 10554.88,860
NetC18_HDNRail_1: C18_HDNRail.1 R38_HDNRail.1 R40_HDNRail.2 U9_HDNRail.2 | length 640.9
  Top Layer w20: U9_HDNRail.2@2505,2824.37 2505,2769.88 2530,2744.88 2660.88,2744.88 2734,2818 2734,2927 2735,2928 2843.12,2928 2875,2959.88 C18_HDNRail.1@2875,3013
NetC18_HDNRail_2: C18_HDNRail.2 R38_HDNRail.2 TP13_HDNRail.1 U8_HDNRail.3 U9_HDNRail.6 | length 2466.6
  Top Layer w20: U9_HDNRail.6@2455,2635.39 2455,2559.88 2480,2534.88 TP13_HDNRail.1@2740,2534.88 ; U8_HDNRail.3@2554.49,2283 2593.12,2283 2650,2339.88 2650,2534.88 TP13_HDNRail.1@2740,2534.88 ; R38_HDNRail.2@2735,3054 2735,3109.88 ; C18_HDNRail.2@2875,3210 2765.12,3210 2735,3179.88 2735,3109.88 ; 2735,3109.88 2740,3114.88 3180,3114.88 3260,3034.88 3260,2819.88 3195,2754.88 2994.88,2754.88 2839.88,2599.88 TP13_HDNRail.1@2805,2599.88 TP13_HDNRail.1@2740,2534.88
NetC18_HDPRail_1: C18_HDPRail.1 R38_HDPRail.1 R40_HDPRail.2 U9_HDPRail.2 | length 640.9
  Top Layer w20: U9_HDPRail.2@4890,2824.37 4890,2769.88 4915,2744.88 5045.88,2744.88 5119,2818 5119,2927 5120,2928 5228.12,2928 5260,2959.88 C18_HDPRail.1@5260,3013
NetC18_HDPRail_2: C18_HDPRail.2 R38_HDPRail.2 TP13_HDPRail.1 U8_HDPRail.3 U9_HDPRail.6 | length 2466.6
  Top Layer w20: U9_HDPRail.6@4840,2635.39 4840,2559.88 4865,2534.88 TP13_HDPRail.1@5125,2534.88 ; U8_HDPRail.3@4939.49,2283 4978.12,2283 5035,2339.88 5035,2534.88 TP13_HDPRail.1@5125,2534.88 ; R38_HDPRail.2@5120,3054 5120,3109.88 ; C18_HDPRail.2@5260,3210 5150.12,3210 5120,3179.88 5120,3109.88 ; 5120,3109.88 5125,3114.88 5565,3114.88 5645,3034.88 5645,2819.88 5580,2754.88 5384.88,2754.88 5229.88,2599.88 TP13_HDPRail.1@5190,2599.88 TP13_HDPRail.1@5125,2534.88
NetC19_HDNRail_1: C19_HDNRail.1 R39_HDNRail.1 R41_HDNRail.2 U8_HDNRail.2 | length 479.2
  Top Layer w20: U8_HDNRail.2@2554.49,2233 R39_HDNRail.1@2705,2233 ; R41_HDNRail.2@2615,2079 2720,2184 2720,2203 2705,2218 R39_HDNRail.1@2705,2233 ; C19_HDNRail.1@2705,2358 R39_HDNRail.1@2705,2233
NetC19_HDNRail_2: C19_HDNRail.2 R27_HDNR_V_DifferentialDriver.1 R30_HDNR_V_DifferentialDriver.1 R39_HDNRail.2 TP12_HDNRail.1 U6_HDNR_V_DifferentialDriver.3 U8_HDNRail.6 | length 3196.4
  Top Layer w20: U8_HDNRail.6@2365.51,2284.88 2425,2284.88 2455,2254.88 v1(2455,2014.88) 2455,1949.88 2550,1854.88 2786.88,1854.88 TP12_HDNRail.1@2820,1888 2820,1870 3030,1660 3030,1240 3150,1120 3180,1120 R30_HDNR_V_DifferentialDriver.1@3164.88,1104.88 ; R39_HDNRail.2@2846,2203 2846,2210 2902,2266 C19_HDNRail.2@2902,2358 ; 3030,1555 3380,1555 3425,1510 U6_HDNR_V_DifferentialDriver.3@3425,1334.88
  Bottom Layer w20: v1(2455,2014.88) 2660,2014.88 2902,2256.88 C19_HDNRail.2@2902,2358
NetC19_HDPRail_1: C19_HDPRail.1 R39_HDPRail.1 R41_HDPRail.2 U8_HDPRail.2 | length 479.2
  Top Layer w20: U8_HDPRail.2@4939.49,2233 5090,2233 ; R41_HDPRail.2@5000,2079 5105,2184 5105,2203 5090,2218 5090,2233 ; C19_HDPRail.1@5090,2358 5090,2233
NetC19_HDPRail_2: C19_HDPRail.2 R27_HDPR_V_DifferentialDriver.1 R30_HDPR_V_DifferentialDriver.1 R39_HDPRail.2 TP12_HDPRail.1 U6_HDPR_V_DifferentialDriver.3 U8_HDPRail.6 | length 3027.1
  Top Layer w20: U8_HDPRail.6@4750.51,2284.88 4810,2284.88 4840,2254.88 v1(4840,2014.88) 4840,1949.88 4935,1854.88 5171.88,1854.88 TP12_HDPRail.1@5205,1888 5205,1550 ; R30_HDPR_V_DifferentialDriver.1@5054.88,1065 5054.88,1070 4945,1179.88 4945,1450 5045,1550 5205,1550 ; R39_HDPRail.2@5231,2203 5231,2210 5287,2266 C19_HDPRail.2@5287,2358 ; U6_HDPR_V_DifferentialDriver.3@5360,1334.88 5360,1439.88 R27_HDPR_V_DifferentialDriver.1@5329.88,1470 5249.88,1550 5205,1550
  Bottom Layer w20: v1(4840,2014.88) 5045,2014.88 5287,2256.88 C19_HDPRail.2@5287,2358
NetC22_HDNRail_2: C22_HDNRail.2 R41_HDNRail.1 | length 705
  Top Layer w20: R41_HDNRail.1@2615,1953 2625,1953 2715,2043 2949,2043 C22_HDNRail.2@3185,1807
NetC22_HDPRail_2: C22_HDPRail.2 R41_HDPRail.1 | length 705
  Top Layer w20: R41_HDPRail.1@5000,1953 5010,1953 5100,2043 5334,2043 C22_HDPRail.2@5570,1807
NetC23_HDNRail_2: C23_HDNRail.2 R40_HDNRail.1 | length 356.5
  Top Layer w20: R40_HDNRail.1@2860,2818 3126,2818 C23_HDNRail.2@3190,2882
NetC23_HDPRail_2: C23_HDPRail.2 R40_HDPRail.1 | length 356.5
  Top Layer w20: R40_HDPRail.1@5245,2818 5511,2818 C23_HDPRail.2@5575,2882
NetC30_1: C30.1 D8.2 R47.1 R48.2 U11.1 | length 1267.1
  Top Layer w20: C30.1@9880,3910 9905.12,3884.88 9905.12,3845.5 9965.12,3785.5 10250,3785.5 10315,3850.5 U11.1@10315,3935.5 10472.5,3935.5 D8.2@10497.5,3910.5 ; R47.1@10535,4090.5 10535,4085.5 10497.5,4048 D8.2@10497.5,3910.5 ; R48.2@10539,3670.5 10497.5,3712 D8.2@10497.5,3910.5
NetC31_2: C31.2 D10.1 R49.1 R50.2 U12.1 | length 969
  Top Layer w20: U12.1@9240,3935.5 9399,3935.5 9409,3925.5 9409,4040.5 ; R49.1@9415,4140.5 9409,4134.5 9409,4040.5 ; D10.1@9685,3660.5 9685,3908 9662.62,3908 9530.12,4040.5 9409,4040.5
NetD2_DR1_3: D2_DR1.3 R5_DR1.2 R6_DR1.2 U1_DR1.6 | length 1253.4
  Top Layer w20: R6_DR1.2@6070,909.65 6080.35,920 v1(6160,920) ; U1_DR1.6@6569.88,1250.75 6570,1250.63 6570,1174.65 R5_DR1.2@6624.88,1119.76 6624.88,1069.88 6639.76,1055 6690,1055 v1(6720,1025) 6848.49,1025 6873.49,1050 6937.99,1050 D2_DR1.3@6945,1057.01
  Bottom Layer w20: v1(6160,920) 6615,920 v1(6720,1025)
NetD2_DR2_3: D2_DR2.3 R5_DR2.2 R6_DR2.2 U1_DR2.6 | length 1210.2
  Top Layer w20: R6_DR2.2@7405,909.76 7420.24,925 v1(7495,925) ; U1_DR2.6@7904.88,1250.87 7904.88,1174.88 R5_DR2.2@7959.88,1119.88 7959.88,1070 7984.88,1045 v1(8020,1045) 8267.87,1045 D2_DR2.3@8280,1057.13
  Bottom Layer w20: v1(7495,925) 7900,925 v1(8020,1045)
NetD2_DR3_3: D2_DR3.3 R5_DR3.2 R6_DR3.2 U1_DR3.6 | length 1318.4
  Top Layer w20: R6_DR3.2@8740,909.76 8755.24,925 v1(8830,925) ; U1_DR3.6@9239.88,1250.87 9239.88,1174.88 R5_DR3.2@9294.88,1119.88 9294.88,1070 9314.88,1050 9430,1050 v1(9455,1025) 9504.63,1025 9536.76,1057.13 D2_DR3.3@9615,1057.13
  Bottom Layer w20: v1(8830,925) 9220,925 9320,1025 v1(9455,1025)
NetD3_DR1_1: D3_DR1.1 D3_DR1.2 R6_DR1.1 R8_DR1.2 U1_DR1.2 | length 911.9
  Top Layer w20: R6_DR1.1@6070,1019.88 6210.12,1019.88 6305.12,1114.88 R8_DR1.2@6305.12,1119.76 ; D3_DR1.1@6072.76,1437.28 D3_DR1.2@6072.76,1362.48 6100.47,1334.76 6340.12,1334.76 6369.88,1305 U1_DR1.2@6369.88,1250.75 ; R8_DR1.2@6305.12,1094.88 6305.12,1109.88 6370.12,1174.88 U1_DR1.2@6370.12,1250.51
NetD3_DR2_1: D3_DR2.1 D3_DR2.2 R6_DR2.1 R8_DR2.2 U1_DR2.2 | length 911.9
  Top Layer w20: R6_DR2.1@7405,1020 7545.12,1020 7640.12,1115 R8_DR2.2@7640.12,1119.88 ; D3_DR2.1@7407.76,1437.4 D3_DR2.2@7407.76,1362.6 7435.47,1334.88 7675.12,1334.88 7704.88,1305.12 U1_DR2.2@7704.88,1250.87 ; R8_DR2.2@7640.12,1095 7640.12,1110 7705.12,1175 U1_DR2.2@7705.12,1250.63
NetD3_DR3_1: D3_DR3.1 D3_DR3.2 R6_DR3.1 R8_DR3.2 U1_DR3.2 | length 911.9
  Top Layer w20: R6_DR3.1@8740,1020 8880.12,1020 8975.12,1115 R8_DR3.2@8975.12,1119.88 ; D3_DR3.1@8742.76,1437.4 D3_DR3.2@8742.76,1362.6 8770.47,1334.88 9010.12,1334.88 9039.88,1305.12 U1_DR3.2@9039.88,1250.87 ; R8_DR3.2@8975.12,1095 8975.12,1110 9040.12,1175 U1_DR3.2@9040.12,1250.63
NetD5_1: D5.1 R12.1 R13.1 | length 887.1
  Top Layer w20: v1@7595,2995 v1(7600,2995) D5.1@7760,2995 ; R13.1@7705,2840 7760,2840 D5.1@7760,2995 ; D5.1@7760,3005 D5.1@7760,2995 ; D5.1@7765,2995 D5.1@7760,2995
  Bottom Layer w20: R12.1@7250,3230 7450,3230 7600,3080 v1(7600,2995)
NetD5_2: D5.2 R13.8 TP4.1 U2.3 | length 1586.4
  Top Layer w10: R13.8@7995,2830 R13.8@7995,2840
  Top Layer w20: U2.3@7245,2905 7245,3055 7280,3090 7905,3090 7930,3065 D5.2@7930,3000 ; R13.8@8005,2830 8005,3000 ; TP4.1@8180,3000 TP4.1@8220,2960
  Top Layer w25: D5.2@7930,3000 8180,3000 8005,3000
NetD6_1: D6.1 R17.1 | length 104
  Top Layer w20: D6.1@7255,2425 R17.1@7255,2529
NetD6_2: D6.2 H1.2 | length 189.1
  Top Layer w20: D6.2@7255,2255 7430,2255 H1.2@7440,2265
NetD13_1: D13.1 R51.1 | length 225
  Top Layer w20: R51.1@5615,280 D13.1@5840,280
NetD13_4: D13.4 R52.2 | length 204
  Top Layer w20: D13.4@5925,180 R52.2@6129,180
NetF3_HDNRail_1: F3_HDNRail.1 P8.4 R42_HDNRail.2 TP11_HDNRail.1 | length 2978.5
  Top Layer w20: F3_HDNRail.1@1840,2744.88 1945,2849.88 2123.12,2849.88 TP11_HDNRail.1@2145,2828 2145,3185 2200,3240 2415,3240 2445,3210 R42_HDNRail.2@2445,3059
  Top Layer w50: F3_HDNRail.1@1840,2744.88 v1(1965,2619.88)
  Bottom Layer w50: P8.4@888,1465 1965,2542 v1(1965,2619.88)
NetF3_HDNRail_2: F3_HDNRail.2 R35_HDNRail.1 R36_HDNRail.1 | length 1080.6
  Top Layer w20: R35_HDNRail.1@1355,3369.88 1400,3369.88 1485,3284.88 1485,2839.88 F3_HDNRail.2@1580,2744.88 1570,2734.88 R36_HDNRail.1@1570,2413
NetF3_HDPRail_1: F3_HDPRail.1 P8.1 R42_HDPRail.2 TP11_HDPRail.1 | length 6215.9
  Top Layer w20: P8.1@415,1470 P8.1@420,1465 ; F3_HDPRail.1@4225,2744.88 4330,2849.88 TP11_HDPRail.1@4508.12,2849.88 ; TP11_HDPRail.1@4530,2828 TP11_HDPRail.1@4508.12,2849.88 ; R42_HDPRail.2@4830,3059 4830,3230 4790,3270 4575,3270 4470,3165 4470,2888 TP11_HDPRail.1@4508.12,2849.88
  Top Layer w50: F3_HDPRail.1@4225,2744.88 4345,2624.88 v1(4345,2575)
  Bottom Layer w50: P8.1@420,1465 420,1285 505,1200 1050,1200 1530,1680 2715,1680 3565,2530 4300,2530 v1(4345,2575)
NetF3_HDPRail_2: F3_HDPRail.2 R35_HDPRail.1 R36_HDPRail.1 | length 1080.6
  Top Layer w20: R35_HDPRail.1@3740,3369.88 3785,3369.88 3870,3284.88 3870,2839.88 F3_HDPRail.2@3965,2744.88 3955,2734.88 R36_HDPRail.1@3955,2413
NetH1_1: H1.1 R9_DR2.1 TP1_DR2.1 U1_DR2.10 | length 1775.3
  Top Layer w20: H1.1@7440,2165 7440,2085 7510,2015 8205,2015 8280,1940 8280,1810 8184.88,1714.88 R9_DR2.1@8170,1714.88 ; U1_DR2.10@7954.88,1609.13 7954.88,1665.04 7998.23,1708.39 8163.5,1708.39 R9_DR2.1@8170,1714.88 ; TP1_DR2.1@8325,1564.88 8267.24,1622.64 8267.24,1617.64 R9_DR2.1@8170,1714.88
NetH1_3: H1.3 R18.2 | length 135
  Top Layer w20: H1.3@7440,2365 R18.2@7440,2500
NetJ1_1: J1.1 R2_DR1.2 R4_DR1.2 | length 1286.6
  Top Layer w20: R4_DR1.2@6625.12,949.76 6625.12,835 R2_DR1.2@6624.88,834.76 6624.88,695.12 6715,605 7379,605 J1.1@7549,435
NetJ1_2: J1.2 R2_DR2.2 R4_DR2.2 | length 743
  Top Layer w20: J1.2@7657,435 7657,537 7730,610 7905,610 7959.88,664.88 R2_DR2.2@7959.88,834.88 7960.12,835.12 R4_DR2.2@7960.12,949.88
NetJ1_3: J1.3 R2_DR3.2 R4_DR3.2 | length 2268.5
  Top Layer w20: J1.3@7765,435 7765,295 7810,250 8040,250 8125,335 8125,475 8200,550 9250,550 9294.88,594.88 R2_DR3.2@9294.88,834.88 9295.12,835.12 R4_DR3.2@9295.12,949.88
NetJ1_6: J1.6 R7_DR1.2 R10_DR1.1 | length 1755.8
  Top Layer w20: R7_DR1.2@6299.88,949.76 6299.88,839.53 6299.88,620.12 6390,530 7311,530 7518,323 J1.6@7603,323
NetJ1_7: J1.7 R7_DR2.2 R10_DR2.1 | length 695.8
  Top Layer w20: R10_DR2.1@7630.12,834.88 7630.12,830.94 7601.42,802.24 7601.42,404.58 7636,370 7664,370 J1.7@7711,323 ; R10_DR2.1@7634.88,839.65 R7_DR2.2@7634.88,949.88
NetJ1_8: J1.8 R7_DR3.2 R10_DR3.1 | length 1662.1
  Top Layer w20: J1.8@7819,323 7819,489 7860,530 7920,530 8010,620 8915,620 8965.12,670.12 R10_DR3.1@8965.12,834.88 ; R10_DR3.1@8969.88,839.65 R7_DR3.2@8969.88,949.88
NetJ4_1: J4.1 R28_HDPR_V_DifferentialDriver.2 | length 1640.5
  Top Layer w20: J4.1@4166,430 4166,440 4166,441 4217,492 4367,492 4485,610 5425.12,610 5535,719.88 R28_HDPR_V_DifferentialDriver.2@5535,864.88
NetJ4_2: J4.2 R28_HDPR_I_DifferentialDriver.2 | length 786
  Top Layer w20: J4.2@4058,430 4058,518 4140,600 4350,600 4480,730 4545,730 4565,750 R28_HDPR_I_DifferentialDriver.2@4565,844.88
NetJ4_3: J4.3 R28_HDNR_V_DifferentialDriver.2 | length 703
  Top Layer w20: R28_HDNR_V_DifferentialDriver.2@3580,879.76 3580,785 3705,660 3865,660 3950,575 3950,445 J4.3@3935,430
